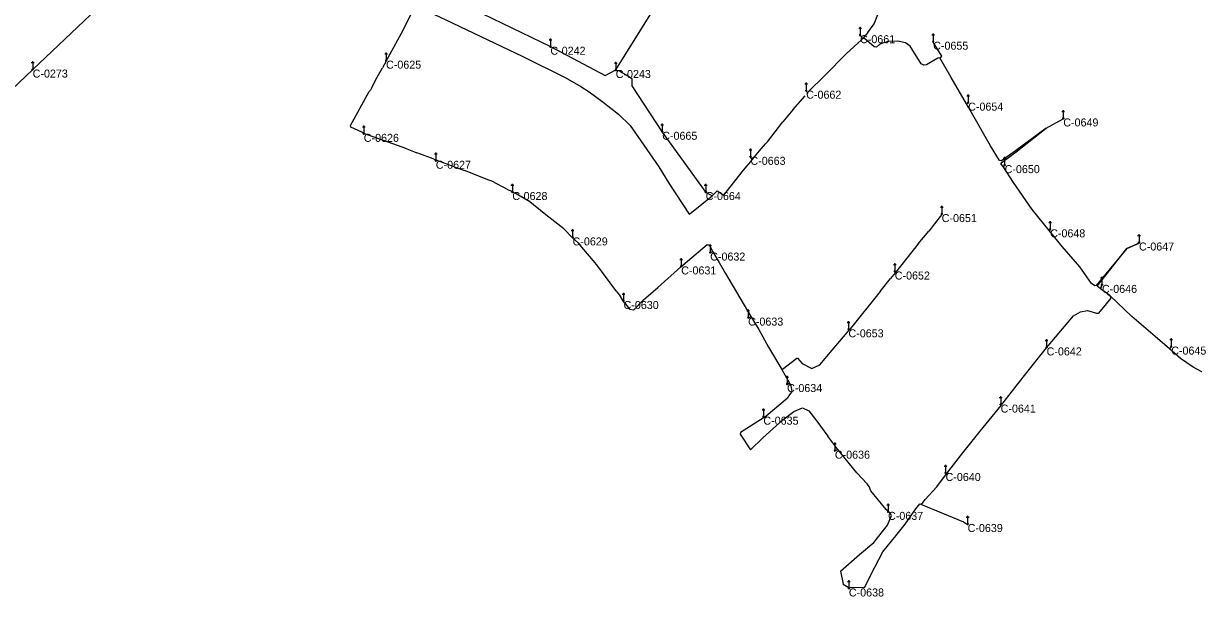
# Model space of a CAD drawing. Extents: x -729889 to -691139, y -995431 to -974354.
# Drawn here: x -725119.9 to -724681.4, y -979987.1 to -979772.4 of the extents above; entities that cross this region are included whole.
import ezdxf

# ---------------------------------------------------------------- set-up
doc = ezdxf.new("R2010")
doc.units = 0
for name, color, linetype in [('Atributy', 7, 'Continuous'), ('Kabelové vedení VO', 7, 'Continuous'), ('Skutečně zaměřené kabelové vedení', 7, 'Continuous'), ('Světelný bod na stožáru sadovém', 7, 'Continuous')]:
    doc.layers.add(name, color=color, linetype=linetype)

# ---------------------------------------------------------------- blocks, each defined once
blk = doc.blocks.new('6.571')
at = {"layer": 'Světelný bod na stožáru sadovém'}
for p, q in [((-0.51, 2.54), (0.51, 2.54)), ((0, 2.54), (0, 0.2))]:
    blk.add_line(p, q, dxfattribs=at)
for points in [[(0.25, 2.54), (0.25, 2.56), (0.25, 2.58), (0.24, 2.6), (0.24, 2.62), (0.23, 2.64), (0.22, 2.66), (0.21, 2.69), (0.19, 2.7), (0.18, 2.72), (0.16, 2.73), (0.15, 2.75), (0.13, 2.76), (0.11, 2.77), (0.09, 2.78), (0.07, 2.78), (0.05, 2.79), (0.02, 2.79), (0, 2.79), (-0.02, 2.79), (-0.05, 2.79), (-0.07, 2.78), (-0.09, 2.78), (-0.11, 2.77), (-0.13, 2.76), (-0.15, 2.75), (-0.16, 2.73), (-0.18, 2.72), (-0.19, 2.7), (-0.21, 2.69), (-0.22, 2.66), (-0.23, 2.64), (-0.24, 2.62), (-0.24, 2.6), (-0.25, 2.58), (-0.25, 2.56), (-0.25, 2.54)], [(-0.2, 0), (-0.17, -0.1), (-0.08, -0.18), (0.04, -0.19), (0.13, -0.14), (0.19, -0.05), (0.18, 0.07), (0.12, 0.15), (0.02, 0.19), (-0.09, 0.17), (-0.17, 0.09), (-0.18, -0.01), (-0.15, -0.1), (-0.06, -0.17), (0.04, -0.17), (0.12, -0.12), (0.17, -0.03), (0.16, 0.08), (0.1, 0.14), (0.01, 0.17), (-0.09, 0.14), (-0.15, 0.07), (-0.16, -0.01), (-0.12, -0.1), (-0.04, -0.15), (0.04, -0.15), (0.12, -0.1), (0.15, -0.01), (0.14, 0.07), (0.08, 0.13), (-0.01, 0.15), (-0.09, 0.12), (-0.13, 0.06), (-0.14, -0.02), (-0.1, -0.1), (-0.03, -0.13), (0.04, -0.13), (0.11, -0.08), (0.13, 0), (0.12, 0.07), (0.06, 0.12), (-0.02, 0.13), (-0.08, 0.1), (-0.12, 0.05), (-0.12, -0.03), (-0.08, -0.09), (-0.02, -0.11), (0.05, -0.11), (0.1, -0.06), (0.11, 0.01), (0.1, 0.06), (0.05, 0.11), (-0.02, 0.11), (-0.07, 0.09), (-0.1, 0.04), (-0.1, -0.03), (-0.06, -0.08), (-0.02, -0.1), (0.05, -0.08), (0.09, -0.04), (0.1, 0.01), (0.08, 0.06), (0.03, 0.09), (-0.02, 0.09), (-0.06, 0.07), (-0.08, 0.02), (-0.08, -0.03), (-0.05, -0.06), (-0.01, -0.08), (0.04, -0.06), (0.07, -0.03), (0.07, 0.01), (0.06, 0.05), (0.02, 0.07), (-0.02, 0.07), (-0.05, 0.05), (-0.07, 0.02), (-0.06, -0.03), (-0.04, -0.05), (0, -0.06), (0.04, -0.04), (0.05, -0.02), (0.06, 0.01), (0.04, 0.04), (0.01, 0.05), (-0.02, 0.05), (-0.04, 0.04), (-0.05, 0.01), (-0.04, -0.02), (-0.02, -0.03), (0.01, -0.04), (0.03, -0.03), (0.04, -0.01), (0.04, 0.01), (0.02, 0.03), (0.01, 0.04), (-0.01, 0.03), (-0.02, 0.02), (-0.03, 0.01), (-0.02, -0.01), (-0.01, -0.02)], [(-0.01, -0.02), (0.01, -0.02), (0.01, -0.01), (0.02, 0), (0.02, 0.01), (0.01, 0.02), (0, 0.02), (-0.01, 0.01), (-0.01, 0.01), (-0.01, 0.01)]]:
    blk.add_lwpolyline(points, dxfattribs=at)
blk.add_circle((0, 0), 0.203, dxfattribs=at)

msp = doc.modelspace()

# ---------------------------------------------------------------- linework, layer by layer
at = {"layer": 'Kabelové vedení VO'}
for p, q in [((-724897.94, -979789.8), (-724881.91, -979764.13)), ((-725094.78, -979769.16), (-725116.41, -979789.63)), ((-724947.74, -979768.85), (-724922.42, -979781.08)), ((-725116.41, -979789.63), (-725134.82, -979807.18))]:
    msp.add_line(p, q, dxfattribs=at)
msp.add_lwpolyline([(-724922.42, -979781.08), (-724901.88, -979791.87), (-724897.94, -979789.8)], dxfattribs=at)
at = {"layer": 'Skutečně zaměřené kabelové vedení'}
for p, q in [((-724803.48, -979775.82), (-724805.29, -979778.06)), ((-724803.48, -979775.82), (-724801.05, -979772.53)), ((-724805.28, -979778.06), (-724806.37, -979776.96)), ((-724819.64, -979791.94), (-724811.62, -979783.85)), ((-724984, -979786.51), (-724985.33, -979789.09)), ((-724819.64, -979791.94), (-724821.74, -979794.06)), ((-724989.31, -979796.45), (-724989.86, -979797.36)), ((-724825.93, -979798.41), (-724825.68, -979797.96)), ((-724823.84, -979796.06), (-724825.68, -979797.96)), ((-724823.84, -979796.06), (-724821.74, -979794.06)), ((-724831.57, -979804.74), (-724826.89, -979799.48)), ((-724831.57, -979804.74), (-724835.32, -979809.27)), ((-724841.06, -979816.77), (-724835.32, -979809.27)), ((-724880.5, -979813.13), (-724864.22, -979835.73)), ((-724976.16, -979819.32), (-724972.47, -979820.84)), ((-724846.51, -979823.12), (-724843.39, -979819.38)), ((-724843.39, -979819.38), (-724841.79, -979817.49)), ((-724841.06, -979816.77), (-724841.79, -979817.49)), ((-724958.47, -979826.15), (-724965.25, -979823.66)), ((-724850.03, -979827.41), (-724846.73, -979823.34)), ((-724847.41, -979822.6), (-724846.61, -979823.24)), ((-724958.47, -979826.15), (-724954.63, -979827.44)), ((-724938.18, -979834.74), (-724937.3, -979835.12)), ((-724936.6, -979835.51), (-724937.31, -979835.15)), ((-724935.24, -979836.16), (-724930.8, -979838.78)), ((-724861.8, -979836.99), (-724864.22, -979835.73)), ((-724784.58, -979854.95), (-724780.65, -979850.26)), ((-724914.13, -979852.7), (-724911.97, -979854.65)), ((-724911.97, -979854.65), (-724911.26, -979855.41)), ((-724861.59, -979857.94), (-724859.23, -979861.93)), ((-724859.23, -979861.93), (-724856.85, -979866.06)), ((-724856.85, -979866.06), (-724847.34, -979882.23)), ((-724798.85, -979872.78), (-724794.94, -979867.93)), ((-724793.1, -979865.68), (-724794.94, -979867.93)), ((-724897.57, -979872.99), (-724896.14, -979874.71)), ((-724894.47, -979877.14), (-724892.59, -979879.58)), ((-724887.47, -979875.9), (-724886.69, -979875.22)), ((-724713.74, -979873.66), (-724712.83, -979874.36)), ((-724844.34, -979887.1), (-724840.73, -979893.66)), ((-724840.73, -979893.66), (-724835.69, -979902.09)), ((-724835.46, -979901.92), (-724830.13, -979897.85)), ((-724835.69, -979902.09), (-724835.46, -979901.92)), ((-724833.68, -979907.63), (-724832.86, -979907.1)), ((-724831.94, -979910.33), (-724833.67, -979912.78)), ((-724822.61, -979921.45), (-724818.5, -979927)), ((-724851.28, -979926.3), (-724847.39, -979932.14)), ((-724814.75, -979932.04), (-724818.5, -979927)), ((-724807.56, -979940.8), (-724803.78, -979944.88)), ((-724783.99, -979952.41), (-724783.94, -979952.32)), ((-724809.98, -979983.67), (-724810.57, -979984.21))]:
    msp.add_line(p, q, dxfattribs=at)
for points in [[(-724984, -979786.51), (-724977.45, -979774.65), (-724973.07, -979765.79), (-724972.93, -979765.65), (-724959.18, -979772.17), (-724932.72, -979784.77), (-724916.91, -979792.61), (-724911.03, -979796.02), (-724907.9, -979798.03), (-724902.61, -979801.88), (-724896.9, -979806.34), (-724892.55, -979810.58), (-724888.47, -979816.36), (-724881.79, -979826.18), (-724878.07, -979832.23), (-724870.37, -979843.89), (-724869.57, -979843.19), (-724861.8, -979836.99)], [(-724801.05, -979772.53), (-724799.42, -979768.43), (-724799.61, -979764.36)], [(-724776.47, -979785.3), (-724777.25, -979785.38), (-724781.49, -979787.92), (-724782.52, -979788.09), (-724783.44, -979787.58), (-724787.57, -979780.91), (-724789.32, -979779.64), (-724792.19, -979779.05), (-724795.67, -979779.22), (-724798.01, -979779.77), (-724799.06, -979780.24), (-724800.2, -979781.32), (-724801.07, -979781.19), (-724804.71, -979778.1), (-724805.29, -979778.06), (-724805.84, -979778.59), (-724811.62, -979783.85)], [(-724766.52, -979802.51), (-724772.21, -979792.67), (-724776.47, -979785.3), (-724775.78, -979784.63), (-724778.98, -979779.4)], [(-724989.31, -979796.45), (-724987.32, -979792.55), (-724985.33, -979789.09)], [(-724897.95, -979790.09), (-724896.67, -979790.08), (-724896.09, -979790.44), (-724892.75, -979792.37), (-724891.86, -979793), (-724891.87, -979795.72), (-724880.5, -979813.13)], [(-724993.13, -979813.19), (-724997.2, -979811.32), (-724997.37, -979810.58), (-724993.83, -979804.28), (-724990.28, -979797.88), (-724989.86, -979797.36)], [(-724826.23, -979798.77), (-724825.93, -979798.41), (-724826.56, -979797.76)], [(-724757.53, -979818.25), (-724765.61, -979804.07), (-724766.52, -979802.51), (-724765.89, -979802.21)], [(-724752.79, -979825.97), (-724753.57, -979824.98), (-724753.18, -979824.34), (-724747.84, -979820.48), (-724736.65, -979811.63), (-724730.23, -979808.15)], [(-724976.16, -979819.32), (-724992.33, -979813.59), (-724993.13, -979813.19)], [(-724736.65, -979811.63), (-724748.18, -979820.17), (-724753.36, -979823.92), (-724754.16, -979823.79), (-724757.54, -979818.23)], [(-724965.34, -979824), (-724965.25, -979823.66), (-724966.92, -979822.92), (-724972.47, -979820.84)], [(-724846.73, -979823.34), (-724846.61, -979823.24), (-724846.51, -979823.12)], [(-724938.18, -979834.74), (-724944.3, -979831.53), (-724945.45, -979831.17), (-724954.63, -979827.44)], [(-724861.8, -979836.99), (-724859.92, -979835.11), (-724857.39, -979836.7), (-724856.57, -979835.63), (-724850.03, -979827.41)], [(-724735.57, -979849.99), (-724741.86, -979842.08), (-724748.91, -979832.01), (-724752.79, -979825.97), (-724752.2, -979825.64)], [(-724936.72, -979835.7), (-724936.6, -979835.51), (-724935.24, -979836.16)], [(-724914.13, -979852.7), (-724917.34, -979849.34), (-724924.09, -979844.09), (-724930.8, -979838.78)], [(-724775.78, -979843.98), (-724776.32, -979844.76), (-724780.65, -979850.26)], [(-724701.85, -979854.42), (-724701.82, -979854.66), (-724706.45, -979856.71), (-724717.9, -979870.62), (-724718.47, -979870.67), (-724719.69, -979869.87), (-724724.04, -979863.56), (-724730.71, -979855.97), (-724735.57, -979849.99), (-724735.16, -979849.69), (-724735.15, -979849.48)], [(-724873.51, -979863.61), (-724865.33, -979856.55), (-724863.64, -979855.19), (-724862.94, -979855.35), (-724861.59, -979857.94), (-724862.53, -979858.4)], [(-724784.58, -979854.95), (-724793.1, -979865.68), (-724793.37, -979865.54)], [(-724715.74, -979870.29), (-724715.73, -979870.48), (-724716.26, -979871.82), (-724717.57, -979870.84), (-724706.45, -979856.71), (-724701.82, -979854.66), (-724701.85, -979854.42)], [(-724897.57, -979872.99), (-724904.99, -979862.84), (-724911.26, -979855.41)], [(-724886.69, -979875.22), (-724882.19, -979871.33), (-724873.51, -979863.61)], [(-724798.85, -979872.78), (-724810.44, -979887.37), (-724810.72, -979887.19)], [(-724689.79, -979893.41), (-724689.73, -979893.56), (-724690.47, -979894.26), (-724695.82, -979889.72), (-724704.57, -979882.15), (-724712.83, -979874.36), (-724716.26, -979871.82), (-724715.73, -979870.48), (-724715.74, -979870.29)], [(-724894.47, -979877.14), (-724895.02, -979876.57), (-724896.14, -979874.71)], [(-724887.47, -979875.9), (-724891.29, -979879.77), (-724892.59, -979879.58)], [(-724736.5, -979893.96), (-724726.36, -979881.88), (-724723.75, -979880.39), (-724721.19, -979879.99), (-724717.73, -979880.9), (-724716.95, -979881), (-724712.33, -979875.33), (-724712.83, -979874.36)], [(-724848.33, -979882.76), (-724847.34, -979882.23), (-724844.34, -979887.1)], [(-724830.13, -979897.85), (-724829.88, -979897.85), (-724828.04, -979899.83), (-724824.42, -979901.67), (-724821.4, -979900.32), (-724816.81, -979894.8), (-724810.44, -979887.37)], [(-724753.5, -979915.5), (-724753.7, -979915.75), (-724743.87, -979903.22), (-724736.5, -979893.96)], [(-724666.07, -979897.81), (-724666.08, -979898.02), (-724665.31, -979898.44), (-724667.56, -979901.6), (-724669.38, -979900.67), (-724671.59, -979903.03), (-724676.63, -979903.74), (-724681.6, -979901.23), (-724686.25, -979897.92), (-724690.47, -979894.26), (-724689.73, -979893.56), (-724689.79, -979893.41)], [(-724835.69, -979902.09), (-724832.38, -979907.99), (-724831.94, -979910.33)], [(-724847.39, -979932.14), (-724842.78, -979927.67), (-724835.26, -979920.92), (-724831.19, -979917.83), (-724827.99, -979916.41), (-724825.61, -979917.5), (-724822.61, -979921.45)], [(-724842.6, -979919.86), (-724842.35, -979920.07), (-724833.67, -979912.78)], [(-724773.99, -979941.12), (-724767.87, -979933.31), (-724761.41, -979925.14), (-724753.5, -979915.5), (-724753.69, -979915.35)], [(-724842.35, -979920.07), (-724851.22, -979925.59), (-724851.28, -979926.3)], [(-724807.56, -979940.8), (-724814.75, -979932.04), (-724815.76, -979932.56)], [(-724783.42, -979952.6), (-724782.01, -979950.78), (-724777.67, -979946.05), (-724773.99, -979941.12), (-724774.32, -979940.97)], [(-724795.65, -979955.33), (-724796.6, -979954.44), (-724802.3, -979947.51), (-724803.02, -979945.92), (-724803.78, -979944.88)], [(-724813.69, -979977.54), (-724806.56, -979971.31), (-724801.28, -979966.88), (-724796.15, -979960.34), (-724794.59, -979956.78), (-724795.1, -979955.9), (-724795.65, -979955.33), (-724795.88, -979955.48)], [(-724809.98, -979983.67), (-724804.64, -979983.61), (-724802.33, -979978.94), (-724797.88, -979970.36), (-724793.01, -979964.37), (-724789.44, -979959.99), (-724785.47, -979954.22), (-724783.99, -979952.41)], [(-724783.94, -979952.32), (-724783.32, -979952.66), (-724767.64, -979959.14), (-724766.08, -979960.07)], [(-724813.69, -979977.54), (-724812.66, -979982.44), (-724810.9, -979983.53), (-724809.98, -979983.67)]]:
    msp.add_lwpolyline(points, dxfattribs=at)

# ---------------------------------------------------------------- block references
at = {"layer": 'Světelný bod na stožáru sadovém', "xscale": 1.0016949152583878, "yscale": 1.0016949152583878}
for p in [(-724806.38, -979776.76), (-724778.98, -979779.19), (-724922.42, -979781.08), (-724984, -979786.3), (-725116.41, -979789.63), (-724897.94, -979789.8), (-724826.55, -979797.55), (-724765.88, -979802.02), (-724730.23, -979807.94), (-724992.34, -979813.71), (-724880.51, -979812.94), (-724847.45, -979822.32), (-724965.34, -979823.8), (-724752.2, -979825.43), (-724936.68, -979835.51), (-724864.23, -979835.52), (-724775.77, -979843.77), (-724914.09, -979852.51), (-724735.15, -979849.48), (-724701.85, -979854.42), (-724862.54, -979858.19), (-724873.41, -979863.38), (-724793.37, -979865.29), (-724715.74, -979870.29), (-724894.99, -979876.32), (-724848.32, -979882.55), (-724810.72, -979886.94), (-724736.47, -979893.71), (-724689.79, -979893.41), (-724833.73, -979907.44), (-724753.69, -979915.14), (-724842.6, -979919.67), (-724815.82, -979932.41), (-724774.33, -979940.76), (-724795.89, -979955.33), (-724766.07, -979959.88), (-724810.57, -979984.02)]:
    msp.add_blockref('6.571', p, dxfattribs=at)

# ---------------------------------------------------------------- texts
at = {"layer": 'Atributy'}
for s, p in [('C-0661', (-724806.38, -979779.81)), ('C-0655', (-724778.98, -979782.24)), ('C-0242', (-724922.42, -979784.13)), ('C-0625', (-724984, -979789.35)), ('C-0273', (-725116.41, -979792.68)), ('C-0243', (-724897.94, -979792.85)), ('C-0662', (-724826.55, -979800.6)), ('C-0654', (-724765.88, -979805.07)), ('C-0649', (-724730.23, -979810.99)), ('C-0626', (-724992.34, -979816.77)), ('C-0665', (-724880.51, -979815.99)), ('C-0627', (-724965.34, -979826.85)), ('C-0663', (-724847.45, -979825.37)), ('C-0650', (-724752.2, -979828.48)), ('C-0628', (-724936.68, -979838.56)), ('C-0664', (-724864.23, -979838.57)), ('C-0651', (-724775.77, -979846.82)), ('C-0648', (-724735.15, -979852.53)), ('C-0629', (-724914.09, -979855.56)), ('C-0647', (-724701.85, -979857.47)), ('C-0632', (-724862.54, -979861.24)), ('C-0631', (-724873.41, -979866.43)), ('C-0652', (-724793.37, -979868.34)), ('C-0646', (-724715.74, -979873.35)), ('C-0630', (-724894.99, -979879.38)), ('C-0633', (-724848.32, -979885.6)), ('C-0653', (-724810.72, -979889.99)), ('C-0642', (-724736.47, -979896.77)), ('C-0645', (-724689.79, -979896.46)), ('C-0634', (-724833.73, -979910.49)), ('C-0641', (-724753.69, -979918.19)), ('C-0635', (-724842.6, -979922.72)), ('C-0636', (-724815.82, -979935.46)), ('C-0640', (-724774.33, -979943.81)), ('C-0637', (-724795.89, -979958.38)), ('C-0639', (-724766.07, -979962.93)), ('C-0638', (-724810.57, -979987.07))]:
    msp.add_text(s, height=3, dxfattribs=at).set_placement(p)

doc.saveas('drawing.dxf')
